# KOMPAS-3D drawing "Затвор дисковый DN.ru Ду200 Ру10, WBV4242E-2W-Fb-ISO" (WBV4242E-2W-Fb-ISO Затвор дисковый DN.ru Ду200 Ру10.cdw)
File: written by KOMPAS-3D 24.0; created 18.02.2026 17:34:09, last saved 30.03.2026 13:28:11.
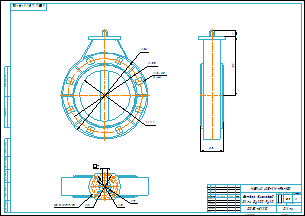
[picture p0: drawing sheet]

Document properties: Автор: R2D2; Форматы листов документа: A2; Полное имя файла: WBV4242E-2W-Fb-ISO Затвор дисковый DN.ru Ду200 Ру10.m3d; Масса: 6.9; Наименование: Затвор дисковый DN.ru Ду200 Ру10; Количество листов документа: 1; Примечание: D050-81210

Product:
- Part/product: Затвор дисковый DN.ru Ду200 Ру10  | designation WBV4242E-2W-Fb-ISO
    Масса: 6.9
    Раздел спецификации: Прочие изделия
    Форматы листов документа: A2
    Примечание: D050-81210

Views: Вид 1, Спереди, Проекционный вид 2, Проекционный вид 3
Referenced files in E:\Работа\Зайцев\WBV4242E-2W-Fb-ISO Затвор дисковый DN.ru Ду50-200 Ру10\DN200\: WBV4242E-2W-Fb-ISO Затвор дисковый DN.ru Ду200 Ру10.m3d
Referenced files in E:\Работа\Зайцев\Для компаса\: чертеж DN.ru А3.cdt
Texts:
  Диаметральный размер
  WBV4242E-2W-Fb-ISO
  ISO 5211 F07/F10
  чертеж DN.ru А3.cdt
  Затвор дисковый
  DN.ru Ду200 Ру10
  Затвор дисковый DN.ru Ду200 Ру10
  WBV4242E-2W-Fb-ISO Затвор дисковый DN.ru Ду200 Ру10
Dimensions and other numbers on the sheet: 0; 3; 2; 4; 340; 291,5; 200; 8 отв.; 89; 231; 22; 8; 102; 90; 70; 17; 1:2; 1; 6,9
